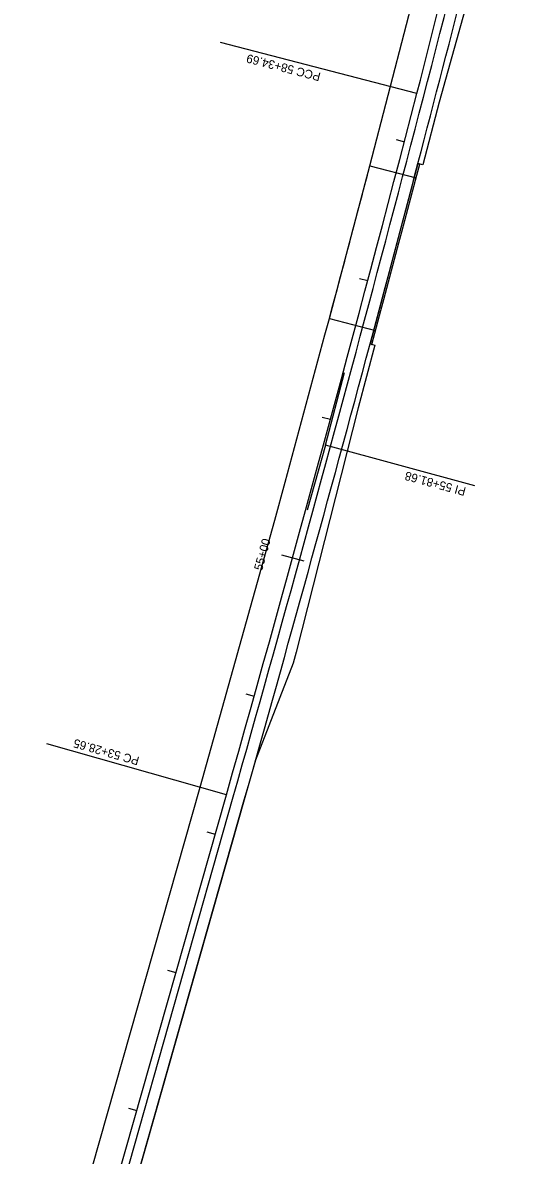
# Model space of a CAD drawing. Extents: x 1445613 to 1446340, y 2042797 to 2056486.
# Drawn here: x 1445891 to 1446235, y 2054904 to 2055693 of the extents above; entities that cross this region are included whole.
import ezdxf

# ---------------------------------------------------------------- set-up
doc = ezdxf.new("R2010")
doc.units = 0
for name, color, linetype in [('20', 7, 'Continuous'), ('Default', 7, 'Continuous'), ('R_Bridge', 7, 'Continuous'), ('R_Horz Alg', 7, 'Continuous'), ('R_Horz Alg Annot', 7, 'Continuous'), ('R_Horz Alg Annot_Detour', 7, 'Continuous'), ('R_Horz Alg Stationing_Detour', 7, 'Continuous'), ('R_Proposed Road', 7, 'Continuous')]:
    doc.layers.add(name, color=color, linetype=linetype)

msp = doc.modelspace()

# ---------------------------------------------------------------- linework, layer by layer
at = {"layer": '20'}
for points in [[(1445891.32, 2054725.14), (1446014.88, 2055160.82), (1446066.81, 2055346.93), (1446074.07, 2055373.43), (1446101.82, 2055475.94), (1446104.9, 2055487.44), (1446133.09, 2055593.77), (1446171.35, 2055741.47)], [(1446208.31, 2055734.63), (1446181.37, 2055638.11), (1446169.94, 2055594.34), (1446166.56, 2055595.23), (1446133.25, 2055469.59), (1446136.63, 2055468.69), (1446124.87, 2055425), (1446081.85, 2055255), (1446079.7, 2055247.28), (1446053.48, 2055179.72), (1446045.66, 2055152.09), (1446045.66, 2055152.09), (1445983.88, 2054934.25), (1445960.45, 2054851.81)]]:
    msp.add_lwpolyline(points, dxfattribs=at)
at = {"layer": 'Default'}
msp.add_arc((1423960.81, 2061415.35), 22923.81, 345.013473, 345.288407, dxfattribs=at)
at = {"layer": 'R_Bridge'}
for p, q in [((1446133.09, 2055593.77), (1446165.23, 2055585.25)), ((1446166.56, 2055595.23), (1446167.77, 2055594.91)), ((1446104.9, 2055487.44), (1446137.04, 2055478.92)), ((1446133.25, 2055469.59), (1446134.46, 2055469.27))]:
    msp.add_line(p, q, dxfattribs=at)
for radius in [22955.81, 22957.06]:
    msp.add_arc((1423960.81, 2061415.35), radius, 344.988739, 345.313141, dxfattribs=at)
at = {"layer": 'R_Horz Alg'}
msp.add_line((1445909.6, 2054719.96), (1446033.15, 2055155.64), dxfattribs=at)
for centre, radius, start, end in [((1440620.51, 2057085.26), 5729.58, 345.4304, 348.5), ((1423960.81, 2061415.35), 22942.81, 344.166667, 345.430397)]:
    msp.add_arc(centre, radius, start, end, dxfattribs=at)
at = {"layer": 'R_Horz Alg Annot'}
for p, q in [((1446102.19, 2055399.06), (1446115.34, 2055449.67)), ((1446102.19, 2055399.06), (1446089.33, 2055353.73)), ((1446206.1, 2055370.83), (1446102.19, 2055399.06))]:
    msp.add_line(p, q, dxfattribs=at)
at = {"layer": 'R_Horz Alg Annot_Detour'}
for points in [[(1446165.84, 2055643.95), (1446029.06, 2055679.5)], [(1446033.15, 2055155.64), (1445908.09, 2055191.11)]]:
    msp.add_lwpolyline(points, dxfattribs=at)
at = {"layer": 'R_Horz Alg Stationing_Detour'}
for points in [[(1446151.29, 2055611.91), (1446157.09, 2055610.39)], [(1446125.78, 2055515.24), (1446131.58, 2055513.7)], [(1446099.85, 2055418.69), (1446105.64, 2055417.12)], [(1446071.58, 2055322.78), (1446087, 2055318.53)], [(1446046.74, 2055225.93), (1446052.51, 2055224.31)], [(1446019.56, 2055129.71), (1446025.34, 2055128.07)], [(1445992.28, 2055033.5), (1445998.05, 2055031.87)], [(1445965, 2054937.3), (1445970.77, 2054935.66)]]:
    msp.add_lwpolyline(points, dxfattribs=at)
at = {"layer": 'R_Proposed Road'}
for p, q in [((1445914.41, 2054718.59), (1446037.96, 2055154.27)), ((1445922.1, 2054716.41), (1446045.66, 2055152.09))]:
    msp.add_line(p, q, dxfattribs=at)
for radius, start, end in [(22947.81, 344.166667, 346), (22955.81, 345.31315, 346), (22955.81, 344.166667, 344.988739)]:
    msp.add_arc((1423960.81, 2061415.35), radius, start, end, dxfattribs=at)

# ---------------------------------------------------------------- texts
at = {"layer": 'R_Horz Alg Annot_Detour'}
for s, rotation, p in [('PCC 58+34.69', 165.4304, (1446099.25, 2055658.31)), ('PI 55+81.68', 164.76498, (1446200.42, 2055369.43)), ('PC 53+28.65', 164.16667, (1445972.98, 2055181.8))]:
    msp.add_text(s, height=6, rotation=rotation, dxfattribs=at).set_placement(p)
at = {"layer": 'R_Horz Alg Stationing_Detour'}
msp.add_text('55+00', height=6, rotation=74.59458, dxfattribs=at).set_placement((1446058.05, 2055311.32))

doc.saveas('drawing.dxf')
